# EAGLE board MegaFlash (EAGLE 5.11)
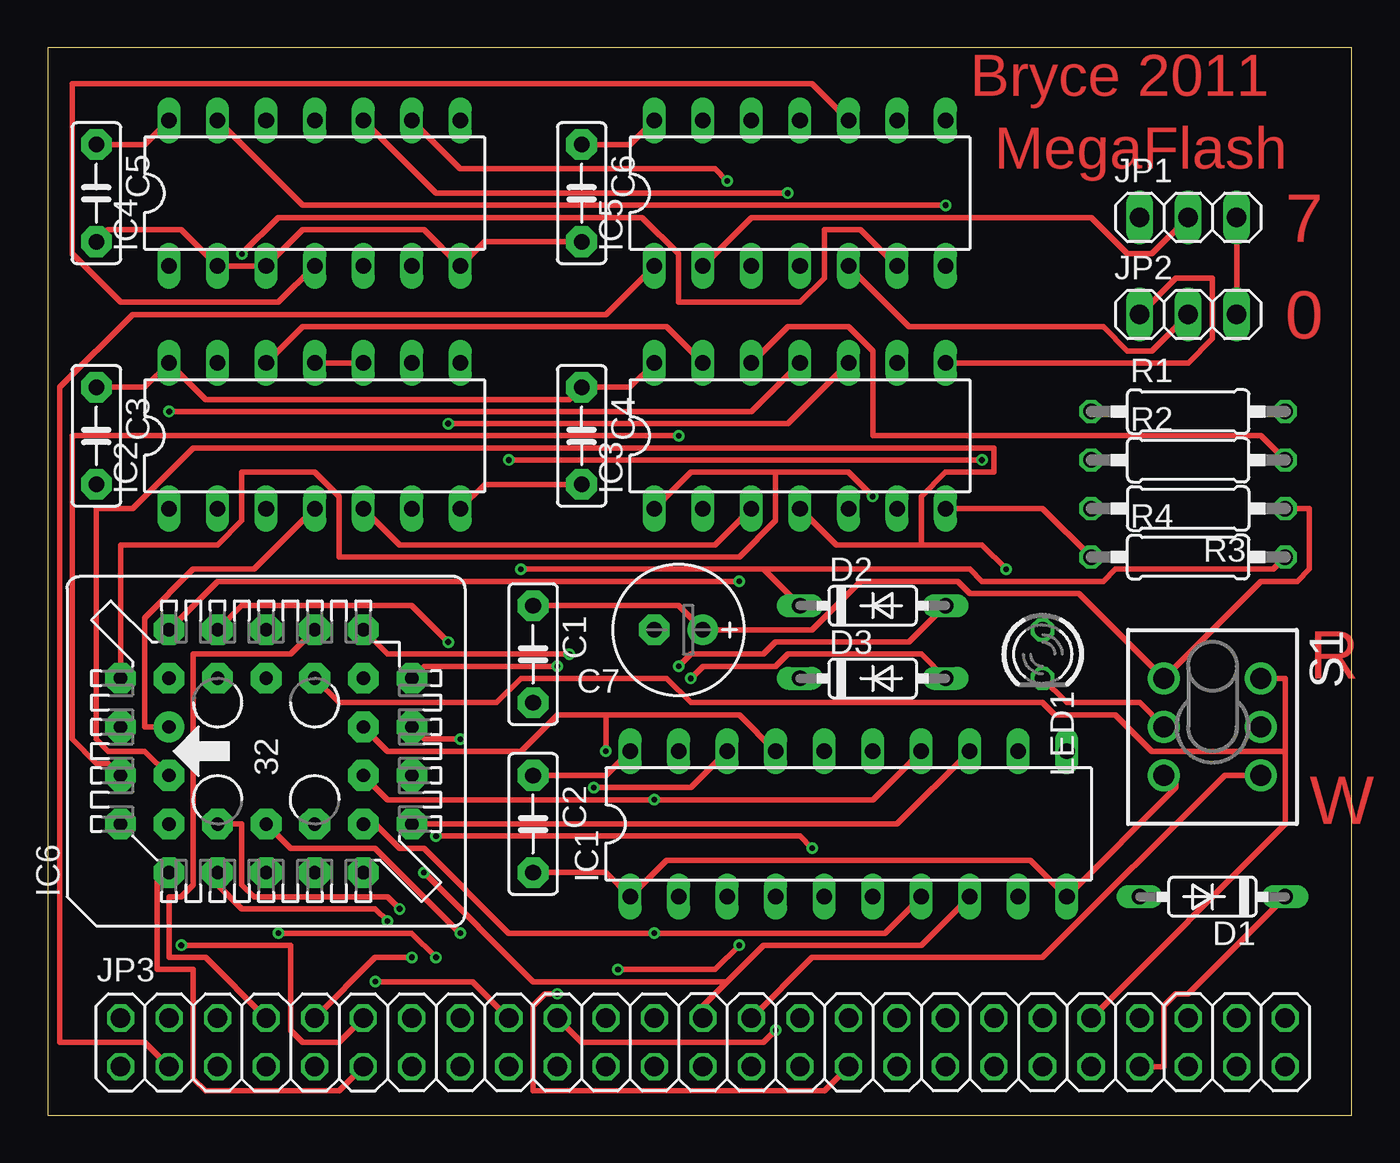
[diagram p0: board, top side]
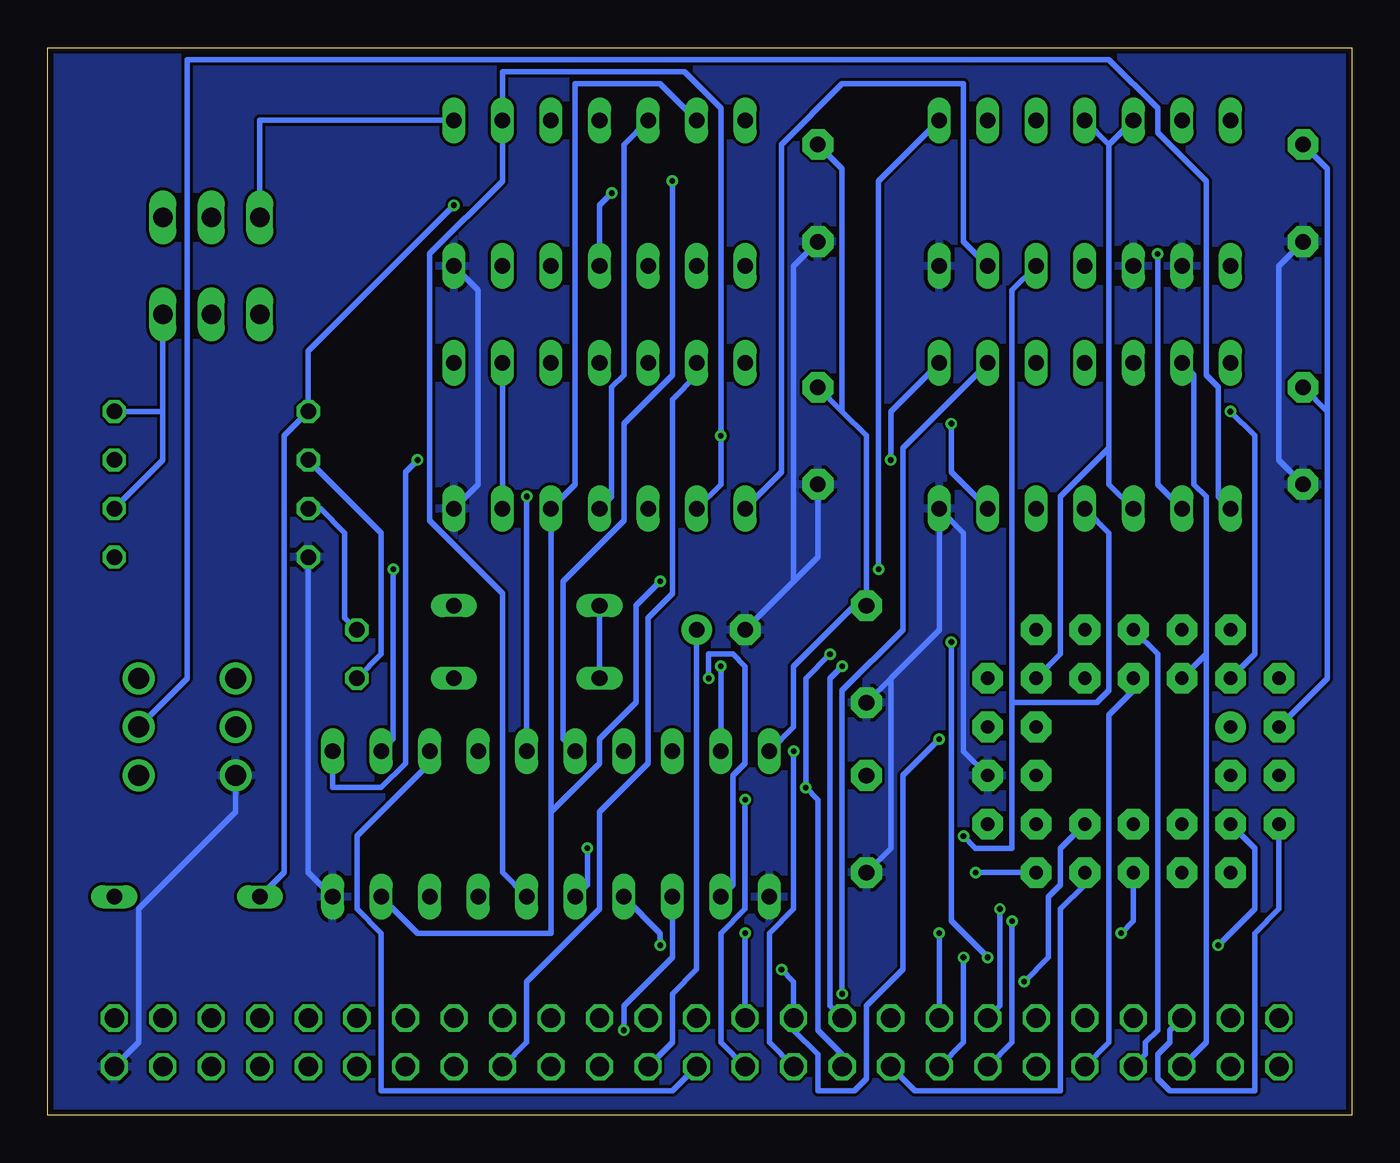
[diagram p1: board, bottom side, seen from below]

Size 68.25 x 55.87 mm. Coordinates in mm from the lower left corner, seen from the top.
Outline: 0,0 68.25,0 68.25,55.87 0,55.87 0,0
Copper layers (1*16): Top 0.035mm / dielectric 1.5mm / Bottom 0.035mm
Design rules "PCB-POOL Standard *": minimum track width 0.3mm, minimum drill 0.3mm, track to track 0.15mm, track to pad 0.15mm, pad to pad 0.15mm, via to via 0.15mm, smd to smd 0.15mm, copper to edge 0.3mm, drill to drill 0.2mm, minimum pad ring 0.2mm, minimum via ring 0.15mm, stop-mask expansion 0.075mm, vias tented up to drill 0mil, thermal gap 0.2mm

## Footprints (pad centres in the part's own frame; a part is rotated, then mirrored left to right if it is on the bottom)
C5B2.5 = drill 0.813 pad 1.6 octagon: 1 -2.54,0; 2 2.54,0
E2,5-7 = drill 0.813 pad 1.6 round: + -1.27,0 | drill 0.813 pad 1.6 octagon: - 1.27,0
DO35-7 = drill 0.813 long: A 3.81,0; C -3.81,0
DIL20 = drill 0.813 long: 1 -11.43,-3.81; 2 -8.89,-3.81; 3 -6.35,-3.81; 4 -3.81,-3.81; 5 -1.27,-3.81; 6 1.27,-3.81; 7 3.81,-3.81; 8 6.35,-3.81; 9 8.89,-3.81; 10 11.43,-3.81; 11 11.43,3.81; 12 8.89,3.81; 13 6.35,3.81; 14 3.81,3.81; 15 1.27,3.81; 16 -1.27,3.81; 17 -3.81,3.81; 18 -6.35,3.81; 19 -8.89,3.81; 20 -11.43,3.81
DIL14 = drill 0.813 long: 1 -7.62,-3.81; 2 -5.08,-3.81; 3 -2.54,-3.81; 4 0,-3.81; 5 2.54,-3.81; 6 5.08,-3.81; 7 7.62,-3.81; 8 7.62,3.81; 9 5.08,3.81; 10 2.54,3.81; 11 0,3.81; 12 -2.54,3.81; 13 -5.08,3.81; 14 -7.62,3.81
PLCC-SR32 = drill 0.7 pad 1.6 round: 1 1.27,5.08 | drill 0.7 pad 1.6 octagon: 2 -1.27,7.62; 3 -1.27,5.08; 4 -3.81,7.62; 5 -6.35,5.08; 6 -3.81,5.08; 7 -6.35,2.54; 8 -3.81,2.54; 9 -6.35,0; 10 -3.81,0; 11 -6.35,-2.54; 12 -3.81,-2.54; 13 -6.35,-5.08; 14 -3.81,-7.62; 15 -3.81,-5.08; 16 -1.27,-7.62; 17 -1.27,-5.08; 18 1.27,-7.62; 19 1.27,-5.08; 20 3.81,-7.62; 21 6.35,-5.08; 22 3.81,-5.08; 23 6.35,-2.54; 24 3.81,-2.54; 25 6.35,0; 26 3.81,0; 27 6.35,2.54; 28 3.81,2.54; 29 6.35,5.08; 30 3.81,7.62; 31 3.81,5.08; 32 1.27,7.62
1X03 = drill 1.016 long: 1 -2.54,0; 2 0,0; 3 2.54,0
2X25 = drill 1.016 octagon: 1 -30.48,-1.27; 2 -30.48,1.27; 3 -27.94,-1.27; 4 -27.94,1.27; 5 -25.4,-1.27; 6 -25.4,1.27; 7 -22.86,-1.27; 8 -22.86,1.27; 9 -20.32,-1.27; 10 -20.32,1.27; 11 -17.78,-1.27; 12 -17.78,1.27; 13 -15.24,-1.27; 14 -15.24,1.27; 15 -12.7,-1.27; 16 -12.7,1.27; 17 -10.16,-1.27; 18 -10.16,1.27; 19 -7.62,-1.27; 20 -7.62,1.27; 21 -5.08,-1.27; 22 -5.08,1.27; 23 -2.54,-1.27; 24 -2.54,1.27; 25 0,-1.27; 26 0,1.27; 27 2.54,-1.27; 28 2.54,1.27; 29 5.08,-1.27; 30 5.08,1.27; 31 7.62,-1.27; 32 7.62,1.27; 33 10.16,-1.27; 34 10.16,1.27; 35 12.7,-1.27; 36 12.7,1.27; 37 15.24,-1.27; 38 15.24,1.27; 39 17.78,-1.27; 40 17.78,1.27; 41 20.32,-1.27; 42 20.32,1.27; 43 22.86,-1.27; 44 22.86,1.27; 45 25.4,-1.27; 46 25.4,1.27; 47 27.94,-1.27; 48 27.94,1.27; 49 30.48,-1.27; 50 30.48,1.27
LED3MM = drill 0.813 octagon: A -1.27,0; K 1.27,0
0207/10 = drill 0.813 octagon: 1 -5.08,0; 2 5.08,0
TL4XPO = drill 1.1 pad 1.676 round: 1 -2.54,2.54; 2 0,2.54; 3 2.54,2.54; 4 -2.54,-2.54; 5 0,-2.54; 6 2.54,-2.54

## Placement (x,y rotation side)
C1  100nf  [C5B2.5]  25.4,24.13 270 top
C2  100nf  [C5B2.5]  25.4,15.24 270 top
C3  100nf  [C5B2.5]  2.54,35.56 270 top
C4  100nf  [C5B2.5]  27.94,35.56 270 top
C5  100nf  [C5B2.5]  2.54,48.26 270 top
C6  100nf  [C5B2.5]  27.94,48.26 270 top
C7  100µf  [E2,5-7]  33.02,25.4 180 top
D1  [DO35-7]  60.96,11.43 180 top
D2  [DO35-7]  43.18,26.67 0 top
D3  [DO35-7]  43.18,22.86 0 top
IC1  74LS374N  [DIL20]  41.91,15.24 0 top
IC2  74LS32N  [DIL14]  13.97,35.56 0 top
IC3  74LS32N  [DIL14]  39.37,35.56 0 top
IC4  74LS02N  [DIL14]  13.97,48.26 0 top
IC5  74LS20N  [DIL14]  39.37,48.26 0 top
IC6  PLCC SOCKET  [PLCC-SR32]  11.43,19.05 90 top
JP1  7  [1X03]  59.69,46.99 0 top
JP2  0  [1X03]  59.69,41.91 0 top
JP3  EC50  [2X25]  34.29,3.81 0 top
LED1  RED  [LED3MM]  52.07,24.13 270 top
R1  1K  [0207/10]  59.69,36.83 0 top
R2  220R  [0207/10]  59.69,34.29 0 top
R3  1K  [0207/10]  59.69,31.75 180 top
R4  1K  [0207/10]  59.69,29.21 0 top
S1  TL46PO  [TL4XPO]  60.96,20.32 270 top

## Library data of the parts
C1-C6 = capacitor-wima
C7 = resistor
D1-D3 = diode
IC1-IC5 = 74xx-eu
IC6 = am29-memory
JP1-JP3 = pinhead
LED1 = led
R1-R4 = rcl
S1 = switch

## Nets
GND: C1.2 C2.2 C3.2 C4.2 C5.2 C6.2 C7.- IC1.1 IC1.10 IC2.7 IC3.7 IC4.2 IC4.3 IC4.7 IC5.7 IC6.16 JP3.49 R4.1 S1.6
N$1: IC1.18 IC6.21 JP3.19
N$2: IC1.3 IC6.20 JP3.20
N$3: IC1.17 IC6.19 JP3.21
N$4: IC1.4 IC6.18 JP3.22
N$5: IC1.14 IC6.17 JP3.23
N$6: IC1.7 IC6.15 JP3.24
N$7: IC1.13 IC6.14 JP3.25
N$8: IC1.8 IC6.13 JP3.26
N$9: IC5.1 JP3.3
N$10: IC5.2 JP1.2
N$11: D2.A IC1.19
N$12: D3.A IC1.2
N$13: IC1.16 IC4.9
N$14: IC1.5 IC2.4 IC4.5 IC6.1
N$15: IC2.13 IC6.28 JP3.5
N$16: IC2.10 IC2.11
N$17: IC2.9 JP3.31
N$18: IC2.12 IC3.13 JP3.33
N$20: IC1.11 IC2.8
N$21: D2.C D3.C IC4.8 R4.2
N$22: IC2.5 IC3.3
N$23: IC3.8 JP2.1
N$25: IC1.15 IC3.1 IC4.6 IC6.30
N$26: IC4.4 IC5.10
N$27: IC4.10 IC5.4
N$28: IC5.5 JP2.2
N$29: IC5.8 JP1.1
N$30: IC1.6 IC3.2 IC5.9 IC6.2
N$32: IC1.9 IC3.5 IC5.13 IC6.29
N$33: IC2.6 IC3.10
N$34: IC3.6 IC3.9
N$35: IC3.11 IC6.31
N$36: IC6.24 JP3.42 S1.1
N$37: IC6.11 JP3.17
N$38: IC6.9 JP3.15
N$39: IC6.7 JP3.13
N$40: IC6.5 JP3.11
N$41: IC6.26 JP3.9
N$42: IC6.25 JP3.7
N$43: IC3.12 R2.2
N$44: IC6.12 JP3.18
N$45: IC6.10 JP3.16
N$46: IC6.8 JP3.14
N$47: IC6.6 JP3.12
N$48: IC6.27 JP3.10
N$49: IC6.23 JP3.8
N$50: IC6.4 JP3.6
N$51: D1.C JP3.43
N$52: D1.A IC4.13 R1.1
N$53: LED1.K R2.1 S1.5
N$54: LED1.A R3.2
N$55: IC1.12 IC3.4 IC5.12 IC6.3
N$67: JP3.28 S1.3
N$68: IC2.1 S1.2
N$69: IC2.2 IC5.6
N$71: IC2.3 IC4.11 IC4.12 IC6.22
VCC: C1.1 C2.1 C3.1 C4.1 C5.1 C6.1 C7.+ IC1.20 IC2.14 IC3.14 IC4.14 IC5.14 IC6.32 JP1.3 JP2.3 JP3.27 R1.2 R3.1 S1.4

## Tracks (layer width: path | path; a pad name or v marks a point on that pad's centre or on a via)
GND
  Top 0.3: R4.1 52.07,31.75 IC3.7 | S1.6 59.06,17.78 59.06,17.14 IC1.10 51.44,13.33 32.39,13.33 IC1.1 29.21,12.7 C2.2 | C5.2 3.18,46.35 6.98,46.35 IC4.2 IC4.3 13.33,46.35 19.69,46.35 IC4.7 22.86,45.72 C6.2 | IC2.7 22.86,33.02 C4.2
  Bottom 0.3: IC5.7 45.72,43.18 45.72,33.02 IC3.7 | JP3.49 63.5,3.81 63.5,10.79 58.42,15.88 S1.6 | R4.1 54.61,12.7 IC1.10 | C3.2 3.81,34.29 3.81,44.45 C5.2 | IC6.16 20.32,19.05 20.32,30.48 IC2.7 21.59,25.4 24.13,22.86 | 24.13,22.86 C1.2 | 29.21,27.94 27.94,29.21 C4.2 | 29.21,27.94 C7.- | C2.2 24.13,13.97 24.13,22.86 | C6.2 29.21,44.45 29.21,27.94
  pour Bottom: 0,55.88 68.58,55.88 68.58,0 0,0
N$1  (via drill 0.3)
  Top 0.3: IC1.18 33.66,17.14 v28.58,17.14 | IC6.21 17.78,24.13 v27.3,24.13
  Bottom 0.3: JP3.19 26.67,3.18 27.94,4.45 27.94,16.51 v28.58,17.14 28.58,22.86 v27.3,24.13
N$2  (via drill 0.3)
  Top 0.3: v38.1,4.45 37.47,3.81 27.94,3.81 JP3.20 | IC6.20 19.69,23.5 v26.67,23.5
  Bottom 0.3: IC1.3 35.56,8.25 38.1,5.71 v38.1,4.45 | v26.67,23.5 27.3,22.86 27.3,5.71 JP3.20
N$3  (via drill 0.3)
  Top 0.3: IC1.17 36.2,20.96 29.21,20.96 | 29.21,20.96 26.67,20.96 24.77,19.05 17.78,19.05 IC6.19 | v29.21,19.05 29.21,20.96
  Bottom 0.3: JP3.21 30.48,3.81 30.48,9.52 29.21,10.79 v29.21,19.05
N$4  (via drill 0.3)
  Top 0.3: v36.2,8.89 34.93,7.62 v29.84,7.62 | IC6.18 19.69,19.68 v21.59,19.68
  Bottom 0.3: IC1.4 36.2,9.52 v36.2,8.89 | v29.84,7.62 29.21,6.98 JP3.22 29.21,4.45 27.94,3.18 27.94,1.27 26.03,1.27 25.4,1.91 25.4,5.71 23.49,7.62 23.49,17.78 v21.59,19.68
N$5  (via drill 0.3)
  Top 0.3: IC1.14 43.18,16.51 v31.75,16.51 17.78,16.51 IC6.17
  Bottom 0.3: JP3.23 33.02,3.81 33.02,9.52 31.75,10.79 v31.75,16.51
N$6  (via drill 0.3)
  Top 0.3: IC1.7 43.82,9.52 v31.75,9.52 24.13,9.52 19.69,13.97 18.41,13.97 17.15,15.24 IC6.15
  Bottom 0.3: v31.75,9.52 JP3.24
N$7
  Top 0.3: IC1.13 44.45,15.24 IC6.14
  Bottom 0.3: JP3.25 35.56,1.27 50.8,1.27 50.8,9.52 52.07,10.79 52.07,14.61 48.26,18.42 IC1.13
N$8  (via drill 0.3)
  Top 0.3: IC1.8 45.72,8.89 37.47,8.89 35.56,6.98 | 35.56,6.98 34.29,5.71 JP3.26 | v19.69,12.7 25.4,6.98 35.56,6.98
  Bottom 0.3: IC6.13 v19.69,12.7
N$9
  Top 0.3: IC5.1 29.21,41.91 4.45,41.91 0.63,38.1 0.63,3.81 5.08,3.81 JP3.3
N$10
  Top 0.3: IC5.2 36.83,46.99 54.61,46.99 56.52,45.08 57.79,45.08 JP1.2
N$11  (via drill 0.3)
  Top 0.3: v33.02,23.5 33.66,24.13 37.47,24.13 38.1,24.76 45.09,24.76 D2.A
  Bottom 0.3: IC1.19 v33.02,23.5
N$12  (via drill 0.3)
  Top 0.3: v33.66,22.86 34.29,23.5 38.1,23.5 38.73,24.13 45.72,24.13 D3.A
  Bottom 0.3: IC1.2 32.39,12.07 32.39,17.78 31.75,18.42 31.75,23.5 32.39,24.13 33.66,24.13 v33.66,22.86
N$13  (via drill 0.3)
  Top 0.3: v35.56,48.89 34.93,49.53 21.59,49.53 IC4.9
  Bottom 0.3: IC1.16 41.27,19.68 41.27,27.94 38.1,31.11 38.1,36.19 35.56,38.73 v35.56,48.89
N$14  (via drill 0.3)
  Top 0.3: IC2.4 10.79,28.57 7.62,28.57 5.08,26.04 5.08,20.32 IC6.1 | v40.01,13.97 39.37,14.61 v20.32,14.61
  Bottom 0.3: IC1.5 40.01,12.07 v40.01,13.97 | v20.32,14.61 19.69,13.97 17.78,13.97 17.78,21.59 | 17.78,21.59 17.78,43.18 IC4.5 | IC2.4 12.7,30.48 12.7,22.22 13.33,21.59 17.78,21.59
N$15
  Bottom 0.3: IC2.13 8.26,38.73 8.26,33.02 7.62,32.39 7.62,24.13 | 7.62,24.13 IC6.28 | JP3.5 7.62,3.81 7.62,24.13
N$16
  Top 0.3: IC2.11 IC2.10
N$17  (via drill 0.3)
  Top 0.3: v26.67,6.35 26.03,6.35 25.4,5.71 25.4,1.27 40.64,1.27 JP3.31
  Bottom 0.3: IC2.9 23.49,34.92 23.49,25.4 26.67,22.22 v26.67,6.35
N$18
  Top 0.3: IC2.12 13.33,41.28 32.39,41.28 IC3.13
  Bottom 0.3: JP3.33 43.18,3.81 43.18,6.98 39.37,10.79 39.37,15.88 36.83,18.42 36.83,26.04 35.56,27.31 35.56,37.47 34.29,38.73 IC3.13
N$20  (via drill 0.3)
  Top 0.3: v24.13,34.29 v48.9,34.29
  Bottom 0.3: IC2.8 24.13,36.83 v24.13,34.29 | v48.9,34.29 49.53,33.66 49.53,18.42 50.8,17.14 53.34,17.14 IC1.11
N$21  (via drill 0.3)
  Top 0.3: v24.77,28.57 37.47,28.57 | 37.47,28.57 D2.C | R4.2 64.14,28.57 55.88,28.57 55.25,27.94 48.9,27.94 48.26,28.57 37.47,28.57
  Bottom 0.3: D2.C D3.C | IC4.8 24.77,48.89 v24.77,28.57
N$22
  Top 0.3: IC2.5 18.41,29.85 34.93,29.85 IC3.3
N$23
  Top 0.3: IC3.8 59.69,39.37 60.96,40.64 60.96,43.81 59.06,43.81 JP2.1
N$25  (via drill 0.3)
  Top 0.3: v43.18,32.39 41.91,33.66 38.1,33.66 | 38.1,33.66 33.66,33.66 IC3.1 | IC6.30 3.81,29.85 8.89,29.85 10.16,31.11 10.16,33.66 13.97,33.66 15.24,32.39 15.24,29.21 36.2,29.21 38.1,31.11 38.1,33.66
  Bottom 0.3: IC3.1 29.84,33.66 29.84,50.8 26.67,53.97 20.32,53.97 20.32,45.72 IC4.6 | v43.18,32.39 IC1.15
N$26
  Top 0.3: IC4.4 12.06,42.55 3.81,42.55 1.27,45.08 1.27,53.97 40.01,53.97 IC5.10
N$27  (via drill 0.3)
  Top 0.3: IC4.10 20.32,48.26 v38.73,48.26
  Bottom 0.3: v38.73,48.26 39.37,47.62 IC5.4
N$28
  Top 0.3: IC5.5 45.09,41.28 55.25,41.28 56.52,40 57.79,40 JP2.2
N$29
  Bottom 0.3: IC5.8 57.15,52.07 JP1.1
N$30  (via drill 0.3)
  Top 0.3: IC6.2 3.18,18.42 2.54,18.42 1.27,19.68 1.27,35.56 v33.02,35.56
  Bottom 0.3: IC1.6 44.45,12.7 44.45,27.31 48.26,31.11 48.26,45.08 44.45,48.89 IC5.9 44.45,54.61 34.93,54.61 33.02,52.7 v33.02,35.56 33.02,33.02 IC3.2
N$32  (via drill 0.3)
  Top 0.3: IC6.29 8.89,27.94 v36.2,27.94
  Bottom 0.3: IC1.9 48.9,9.52 41.91,9.52 41.91,15.88 | 41.91,15.88 IC3.5 40.64,33.02 40.64,53.97 36.2,53.97 IC5.13 | v36.2,27.94 37.47,26.67 37.47,21.59 39.37,19.68 39.37,18.42 41.91,15.88
N$33  (via drill 0.3)
  Top 0.3: v20.95,36.19 38.73,36.19 IC3.10
  Bottom 0.3: IC2.6 20.95,33.66 v20.95,36.19
N$34
  Bottom 0.3: IC3.6 IC3.9
N$35  (via drill 0.3)
  Top 0.3: IC3.11 36.83,36.83 v6.35,36.83
  Bottom 0.3: v6.35,36.83 5.08,35.56 5.08,24.13 IC6.31
N$36
  Top 0.3: JP3.42 64.77,15.24 64.77,19.05 | 64.77,19.05 64.77,22.86 S1.1 | IC6.24 15.24,21.59 23.49,21.59 24.77,22.86 32.39,22.86 33.66,21.59 52.07,21.59 52.7,20.96 55.88,20.96 57.79,19.05 64.77,19.05
N$37
  Bottom 0.3: JP3.17 22.86,1.27 15.24,1.27 15.24,10.79 13.97,12.07 IC6.11
N$38  (via drill 0.3)
  Top 0.3: v20.32,8.25 19.05,9.52 v12.06,9.52
  Bottom 0.3: JP3.15 20.32,3.81 v20.32,8.25 | v12.06,9.52 11.43,10.16 IC6.9
N$39  (via drill 0.3)
  Top 0.3: v17.78,10.16 17.15,10.79 10.16,10.79 8.89,12.07 IC6.7
  Bottom 0.3: JP3.13 17.78,3.81 v17.78,10.16
N$40
  Top 0.3: JP3.11 15.24,1.27 8.26,1.27 7.62,1.91 7.62,7.62 5.71,7.62 5.71,12.7 IC6.5
N$41
  Bottom 0.3: JP3.9 12.7,3.81 12.7,20.96 11.43,22.22 IC6.26
N$42
  Bottom 0.3: JP3.7 10.79,3.18 10.79,3.81 10.16,4.45 10.16,24.13 IC6.25
N$43
  Top 0.3: IC3.12 38.73,41.28 41.91,41.28 43.18,40 43.18,35.56 63.5,35.56 R2.2
N$44  (via drill 0.3)
  Top 0.3: JP3.18 22.23,6.98 v17.15,6.98
  Bottom 0.3: v17.15,6.98 15.87,8.25 15.87,11.43 15.24,12.07 15.24,13.97 IC6.12
N$45  (via drill 0.3)
  Top 0.3: v21.59,9.52 17.15,13.97 12.7,13.97 IC6.10
  Bottom 0.3: JP3.16 v21.59,9.52
N$46  (via drill 0.3)
  Top 0.3: v18.41,10.79 17.78,11.43 10.79,11.43 10.16,12.07 10.16,15.24 IC6.8
  Bottom 0.3: JP3.14 18.41,5.71 v18.41,10.79
N$47  (via drill 0.3)
  Top 0.3: JP3.12 15.24,3.81 13.33,3.81 12.7,4.45 12.7,8.89 v6.98,8.89
  Bottom 0.3: v6.98,8.89 5.08,10.79 5.08,13.97 IC6.6
N$48  (via drill 0.3)
  Top 0.3: JP3.10 17.15,8.25 v19.05,8.25 | v20.95,24.76 19.05,26.67 10.16,26.67 IC6.27
  Bottom 0.3: v19.05,8.25 20.95,10.16 v20.95,24.76
N$49
  Top 0.3: JP3.8 8.26,8.25 6.35,8.25 6.35,11.43 6.98,11.43 7.62,12.07 7.62,24.13 12.7,24.13 IC6.23
N$50
  Bottom 0.3: JP3.6 9.53,4.45 9.53,3.81 10.16,3.18 10.16,1.91 9.53,1.27 5.08,1.27 5.08,9.52 3.81,10.79 IC6.4
N$51
  Top 0.3: D1.C 59.69,6.35 59.06,6.35 58.42,5.71 58.42,2.54 JP3.43
N$52  (via drill 0.3)
  Top 0.3: IC4.13 13.33,47.62 v46.99,47.62
  Bottom 0.3: v46.99,47.62 54.61,40 R1.1 55.88,35.56 55.88,12.7 D1.A
N$53
  Top 0.3: LED1.K 53.34,21.59 57.15,21.59 S1.5
  Bottom 0.3: R2.1 50.8,30.48 50.8,24.13 LED1.K
N$54
  Bottom 0.3: LED1.A 52.7,26.04 52.7,30.48 53.98,31.75 R3.2
N$55  (via drill 0.3)
  Top 0.3: v50.16,28.57 48.9,29.85 45.72,29.85 | 45.72,29.85 41.27,29.85 IC3.4 | IC6.3 5.08,19.05 3.18,19.05 2.54,19.68 2.54,31.75 4.45,31.75 7.62,34.92 49.53,34.92 49.53,33.66 46.99,33.66 45.72,32.39 45.72,29.85
  Bottom 0.3: IC3.4 38.73,32.39 38.73,38.1 38.1,38.73 38.1,50.8 IC5.12 | IC1.12 50.16,19.68 v50.16,28.57
N$67
  Top 0.3: JP3.28 40.01,8.25 52.07,8.25 61.59,17.78 S1.3
N$68
  Bottom 0.3: IC2.1 6.98,32.39 6.98,38.1 7.62,38.73 7.62,48.89 10.16,51.44 10.16,52.7 12.7,55.24 60.96,55.24 60.96,22.86 S1.2
N$69  (via drill 0.3)
  Top 0.3: v10.16,45.08 12.06,46.99 31.12,46.99 33.02,45.08 33.02,42.55 39.37,42.55 40.64,43.81 40.64,46.35 42.55,46.35 IC5.6
  Bottom 0.3: IC2.2 10.16,33.02 v10.16,45.08
N$71
  Bottom 0.3: IC2.3 12.7,33.02 12.7,34.92 | 12.7,34.92 12.7,50.8 | 12.7,50.8 IC4.12 | 12.7,50.8 IC4.11 | IC6.22 15.24,24.13 15.24,32.39 12.7,34.92
VCC
  Top 0.3: IC4.14 5.08,50.8 C5.1 | C3.1 5.08,38.1 IC2.14 8.26,37.47 27.3,37.47 C4.1 30.48,38.1 IC3.14 | JP2.3 JP1.3 | R3.1 66.04,31.75 66.04,28.57 65.41,27.94 63.5,27.94 S1.4 53.98,27.31 48.26,27.31 47.62,27.94 42.55,27.94 40.01,25.4 C7.+ 33.02,26.67 C1.1 | IC1.20 29.21,17.78 C2.1 | IC5.14 30.48,50.8 C6.1
  Bottom 0.3: IC6.32 1.27,22.86 1.27,36.83 | 1.27,36.83 C3.1 | C5.1 1.27,49.53 1.27,36.83 | R3.1 62.23,34.29 62.23,36.83 | 62.23,36.83 JP2.3 | 62.23,36.83 R1.2 | JP3.27 35.56,3.81 35.56,6.35 34.29,7.62 C7.+ | 26.67,36.83 25.4,35.56 25.4,27.31 | C4.1 26.67,36.83 | C6.1 26.67,49.53 26.67,36.83 | IC1.20 29.21,20.32 29.21,23.5 25.4,27.31 | 25.4,27.31 C1.1

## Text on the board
Top: Bryce 2011 | MegaFlash | 7 | 0 | R | W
